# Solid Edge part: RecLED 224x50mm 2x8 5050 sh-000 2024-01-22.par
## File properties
Author: jaroslaw.przewlocki
Template: iso metric part.par
Last saved by: jaroslaw.przewlocki
Revision: 2
Application: Solid Edge
Gęstość: 0,000 kg/m^3
Dokładność: 0,990
Username: jaroslaw.przewlocki
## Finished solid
Body 1: solid body, 1023 faces, 2587 edges, 1638 vertices.
  Faces by surface: plane 495, cylinder 267, torus 104, cone 88, spline 47, sphere 20, swept 2
  Edges by curve: line 1332, curve on surface 677, circle 286, spline 160, ellipse 132
Bounding box of the edges (mm; curved faces can reach further): 49.500 x 4.950 x 223.000, from (-24.75, -3.45, -111.5) to (24.75, 1.5, 111.5).
Cylindrical faces by radius (mm): R0.199 x2, R0.2 x78, R0.2002 x4, R0.2169 x6, R0.25 x24, R0.3 x4, R0.3373 x6, R0.4 x16, R0.4006 x4, R0.4008 x4, R0.525 x4, R0.6 x24, R1 x14, R1.05 x16, R1.0894 x4, R1.0991 x8, R1.1 x28, R1.5342 x3, R1.5343 x1, R1.7452 x1, R1.7456 x2, R1.75 x4, R3.7549 x1, R5.3685 x1, R5.3987 x1, R5.4728 x1, R5.8982 x1, R7.5931 x1, R7.8648 x1, R8.5931 x1, R10.3711 x1, R11.964 x1
Conical faces (half-angle, radius in mm at the cone's reference point): 0.3913 deg R1.0968 x4, 0.447 deg R1.0952 x4, 0.464 deg R1.0955 x4, 0.5 deg R0.5056 x8, 0.5 deg R1.0082 x8, 1 deg R0.5511 x4, 10 deg R0.2132 x4, 10 deg R0.4132 x4, 15.6748 deg R1.1041 x2, 15.6751 deg R1.1041 x2, 15.7937 deg R1.1267 x2, 15.7938 deg R1.1267 x2, 18.4844 deg R1.0657 x8, 18.9316 deg R0.5099 x4, 19.4337 deg R0.5111 x4, 27.363 deg R0.6214 x4, 40.1968 deg R0.519 x2, 40.228 deg R0.5176 x2, 42.9179 deg R0.4919 x2, 42.9331 deg R0.4916 x2, 45 deg R0.575 x4, 45 deg R0.625 x8
Toroidal faces (ring radius, tube radius in mm): R0.0958 r0.3997 x8, R0.1 r0.2 x2, R0.1075 r0.4 x4, R0.1101 r0.4001 x4, R0.1216 r0.4 x4, R0.1234 r0.4 x4, R0.1634 r0.2287 x2, R0.1641 r0.2287 x2, R0.3286 r0.2001 x2, R0.3702 r0.4 x4, R0.3818 r0.2 x4, R0.4163 r0.3984 x4, R0.4824 r0.2001 x2, R0.4952 r0.2 x2, R0.6008 r0.3968 x4, R0.6009 r0.3969 x4, R0.6227 r0.2 x2, R0.6235 r0.2 x2, R0.8 r0.2 x8, R0.8522 r0.3 x4, R0.9002 r0.2 x2, R0.9018 r0.2 x2, R0.9181 r0.2227 x4, R0.9197 r0.223 x2, R0.9199 r0.223 x2, R0.9663 r0.2263 x2, R0.9665 r0.2263 x2, R1.3 r0.2 x4, R1.327 r1.1 x4, R1.3271 r1.1 x4, R1.8741 r0.2175 x2, R1.8987 r0.2 x2
Spherical faces by radius (mm): R0.2 x16, R0.6 x4
Planar faces by outward normal: +x 49, +y 15, +z 45, -x 49, -y 81, -z 64, oblique 192
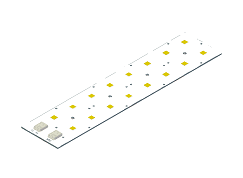
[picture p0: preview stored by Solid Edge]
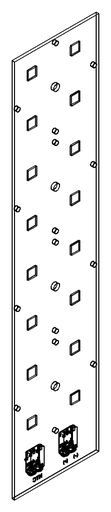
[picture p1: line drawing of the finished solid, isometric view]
